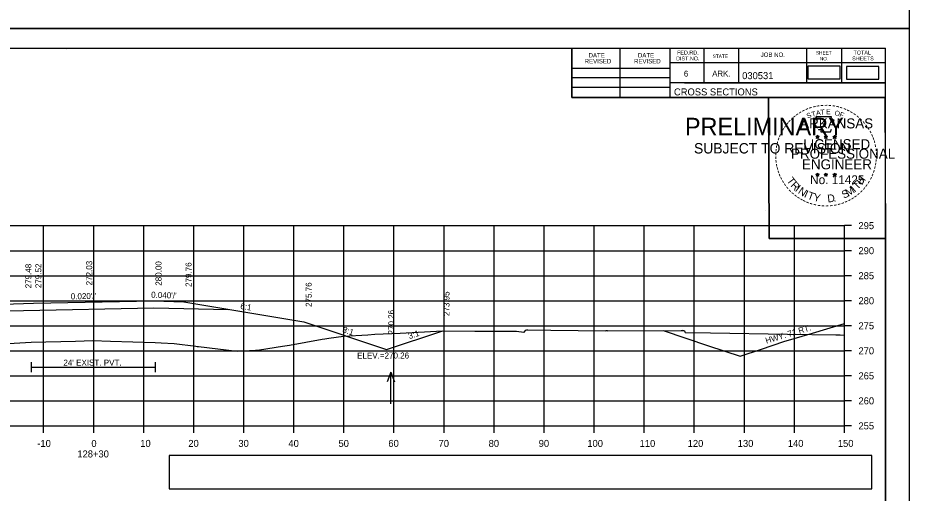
# Model space of a CAD drawing. Extents: x 285 to 4233, y -659 to 3710.
# Drawn here: x 524.1 to 702.2, y 1590.1 to 1685 of the extents above; entities that cross this region are included whole.
import ezdxf

# ---------------------------------------------------------------- set-up
doc = ezdxf.new("R2010")
doc.units = 0
for name, color, linetype in [('R_Alt Surface', 7, 'Continuous'), ('R_Axis', 7, 'Continuous'), ('R_Axis Annot', 7, 'Continuous'), ('R_Border', 7, 'Continuous'), ('R_Border PE', 7, 'Continuous'), ('R_Border Prem', 7, 'Continuous'), ('R_Exist Surface', 7, 'Continuous'), ('R_Fin Surface', 7, 'Continuous'), ('R_Grid', 7, 'Continuous'), ('R_No Plot', 7, 'Continuous'), ('R_Proposed Const Limits', 7, 'Continuous'), ('R_Water', 7, 'Continuous'), ('R_Water Annot', 7, 'Continuous'), ('R_Xsect Elev', 7, 'Continuous'), ('R_Xsect Slope', 7, 'Continuous')]:
    doc.layers.add(name, color=color, linetype=linetype)

msp = doc.modelspace()

# ---------------------------------------------------------------- linework, layer by layer
at = {"layer": 'R_Alt Surface'}
for points in [[(508.71, 1626.25), (517.28, 1626.42), (525.28, 1626.58), (551.28, 1627.1), (551.28, 1627.1), (557.28, 1626.98), (566.12, 1626.8)], [(526.81, 1616.22), (526.81, 1614.22)], [(551.58, 1616.22), (551.58, 1614.22)], [(526.81, 1615.22), (551.58, 1615.22)]]:
    msp.add_lwpolyline(points, dxfattribs=at)
at = {"layer": 'R_Axis'}
for p, q in [((689.28, 1603.52), (689.28, 1643.52)), ((690.68, 1643.52), (689.28, 1643.52)), ((690.68, 1638.52), (689.28, 1638.52)), ((690.68, 1633.52), (689.28, 1633.52)), ((690.68, 1628.52), (689.28, 1628.52)), ((690.68, 1623.52), (689.28, 1623.52)), ((690.68, 1618.52), (689.28, 1618.52)), ((690.68, 1613.52), (689.28, 1613.52)), ((690.68, 1608.52), (689.28, 1608.52)), ((389.28, 1603.52), (689.28, 1603.52)), ((529.28, 1602.12), (529.28, 1603.52)), ((539.28, 1602.12), (539.28, 1603.52)), ((549.28, 1602.12), (549.28, 1603.52)), ((559.28, 1602.12), (559.28, 1603.52)), ((569.28, 1602.12), (569.28, 1603.52)), ((579.28, 1602.12), (579.28, 1603.52)), ((589.28, 1602.12), (589.28, 1603.52)), ((599.28, 1602.12), (599.28, 1603.52)), ((609.28, 1602.12), (609.28, 1603.52)), ((619.28, 1602.12), (619.28, 1603.52)), ((629.28, 1602.12), (629.28, 1603.52)), ((639.28, 1602.12), (639.28, 1603.52)), ((649.28, 1602.12), (649.28, 1603.52)), ((659.28, 1602.12), (659.28, 1603.52)), ((669.28, 1602.12), (669.28, 1603.52)), ((679.28, 1602.12), (679.28, 1603.52)), ((689.28, 1602.12), (689.28, 1603.52)), ((690.68, 1603.52), (689.28, 1603.52))]:
    msp.add_line(p, q, dxfattribs=at)
at = {"layer": 'R_Axis Annot'}
for points in [[(681.96, 1672.82), (688.42, 1672.82), (688.42, 1675.38), (681.96, 1675.38)], [(689.66, 1672.76), (696.12, 1672.76), (696.12, 1675.32), (689.66, 1675.32)], [(554.36, 1590.93), (694.72, 1590.93), (694.72, 1597.58), (554.36, 1597.58)]]:
    msp.add_lwpolyline(points, close=True, dxfattribs=at)
at = {"layer": 'R_Border'}
for p, q in [((381.28, 1678.98), (697.46, 1678.98)), ((533.8, 1678.72), (533.8, 1678.72)), ((533.8, 1678.72), (533.8, 1678.72)), ((634.82, 1669.1), (634.82, 1678.98)), ((644.5, 1669.1), (644.5, 1678.98)), ((654.36, 1678.98), (654.36, 1669.1)), ((661.2, 1678.98), (661.2, 1672.04)), ((668.14, 1678.98), (668.14, 1672.04)), ((681.72, 1678.98), (681.72, 1672.04)), ((688.66, 1678.98), (688.66, 1672.04)), ((697.46, 1473.52), (697.46, 1678.98)), ((697.46, 1676.04), (654.36, 1676.04)), ((697.46, 1676.06), (697.46, 1676.06)), ((634.82, 1674.96), (654.36, 1674.96)), ((634.82, 1673.1), (654.36, 1673.1)), ((634.82, 1671.16), (654.36, 1671.16)), ((697.46, 1672.04), (654.36, 1672.04)), ((657.32, 1672.04), (697.46, 1672.04)), ((697.46, 1669.1), (634.82, 1669.1))]:
    msp.add_line(p, q, dxfattribs=at)
at = {"layer": 'R_Border PE'}
for p, q in [((683.89, 1661.61), (683.85, 1661.36)), ((683.89, 1661.24), (683.89, 1661.61)), ((683.89, 1661.61), (683.94, 1661.36)), ((685.56, 1661.61), (685.52, 1661.36)), ((685.56, 1661.24), (685.56, 1661.61)), ((685.56, 1661.61), (685.61, 1661.36)), ((687.33, 1661.6), (687.29, 1661.34)), ((687.33, 1661.23), (687.33, 1661.6)), ((687.33, 1661.6), (687.38, 1661.35)), ((683.54, 1661.35), (683.89, 1661.24)), ((683.54, 1661.35), (683.8, 1661.31)), ((683.54, 1661.35), (683.78, 1661.23)), ((683.68, 1660.95), (683.89, 1661.24)), ((683.68, 1660.95), (683.8, 1661.19)), ((683.68, 1660.95), (683.89, 1661.16)), ((684.24, 1661.35), (683.89, 1661.24)), ((684.11, 1660.95), (683.89, 1661.24)), ((684.11, 1660.95), (683.89, 1661.16)), ((684.24, 1661.35), (683.95, 1661.3)), ((684.11, 1660.95), (683.97, 1661.24)), ((684.24, 1661.35), (684.04, 1661.25)), ((685.21, 1661.35), (685.56, 1661.24)), ((685.21, 1661.35), (685.47, 1661.31)), ((685.21, 1661.35), (685.45, 1661.23)), ((685.35, 1660.95), (685.56, 1661.24)), ((685.35, 1660.95), (685.47, 1661.19)), ((685.35, 1660.95), (685.56, 1661.16)), ((685.91, 1661.35), (685.56, 1661.24)), ((685.78, 1660.95), (685.56, 1661.24)), ((685.78, 1660.95), (685.56, 1661.16)), ((685.91, 1661.35), (685.62, 1661.3)), ((685.78, 1660.95), (685.64, 1661.24)), ((685.91, 1661.35), (685.71, 1661.25)), ((686.98, 1661.34), (687.33, 1661.23)), ((686.98, 1661.34), (687.23, 1661.3)), ((686.98, 1661.34), (687.22, 1661.22)), ((687.11, 1660.93), (687.33, 1661.23)), ((687.11, 1660.93), (687.24, 1661.18)), ((687.11, 1660.93), (687.33, 1661.15)), ((687.67, 1661.34), (687.33, 1661.23)), ((687.54, 1660.93), (687.33, 1661.23)), ((687.54, 1660.93), (687.33, 1661.15)), ((687.67, 1661.34), (687.39, 1661.29)), ((687.54, 1660.93), (687.4, 1661.22)), ((687.67, 1661.34), (687.47, 1661.24)), ((683.54, 1653.78), (683.89, 1653.67)), ((683.54, 1653.78), (683.79, 1653.74)), ((683.54, 1653.78), (683.78, 1653.66)), ((683.67, 1653.37), (683.89, 1653.67)), ((683.67, 1653.37), (683.8, 1653.62)), ((683.67, 1653.37), (683.89, 1653.59)), ((683.89, 1654.03), (683.85, 1653.78)), ((683.89, 1653.67), (683.89, 1654.03)), ((683.89, 1654.03), (683.94, 1653.78)), ((684.24, 1653.78), (683.89, 1653.67)), ((684.1, 1653.37), (683.89, 1653.67)), ((684.1, 1653.37), (683.89, 1653.59)), ((684.24, 1653.78), (683.95, 1653.73)), ((684.1, 1653.37), (683.97, 1653.66)), ((684.24, 1653.78), (684.03, 1653.68)), ((685.21, 1653.78), (685.56, 1653.67)), ((685.21, 1653.78), (685.46, 1653.74)), ((685.21, 1653.78), (685.45, 1653.66)), ((685.34, 1653.37), (685.56, 1653.67)), ((685.34, 1653.37), (685.47, 1653.62)), ((685.34, 1653.37), (685.56, 1653.59)), ((685.56, 1654.03), (685.52, 1653.78)), ((685.56, 1653.67), (685.56, 1654.03)), ((685.56, 1654.03), (685.61, 1653.78)), ((685.91, 1653.78), (685.56, 1653.67)), ((685.77, 1653.37), (685.56, 1653.67)), ((685.77, 1653.37), (685.56, 1653.59)), ((685.91, 1653.78), (685.62, 1653.73)), ((685.77, 1653.37), (685.63, 1653.66)), ((685.91, 1653.78), (685.7, 1653.68)), ((686.98, 1653.77), (687.33, 1653.66)), ((686.98, 1653.77), (687.23, 1653.73)), ((686.98, 1653.77), (687.21, 1653.65)), ((687.11, 1653.36), (687.33, 1653.66)), ((687.11, 1653.36), (687.24, 1653.61)), ((687.11, 1653.36), (687.32, 1653.58)), ((687.33, 1654.02), (687.28, 1653.77)), ((687.54, 1653.36), (687.32, 1653.58)), ((687.33, 1653.66), (687.33, 1654.02)), ((687.33, 1654.02), (687.37, 1653.77)), ((687.67, 1653.77), (687.33, 1653.66)), ((687.54, 1653.36), (687.33, 1653.66)), ((687.67, 1653.77), (687.39, 1653.72)), ((687.54, 1653.36), (687.4, 1653.65)), ((687.67, 1653.77), (687.47, 1653.67))]:
    msp.add_line(p, q, dxfattribs=at)
for points in [[(683.59, 1665.23), (683.85, 1664.4)], [(687.1, 1664.31), (687.24, 1664.59), (686.55, 1664.57), (686.7, 1665.23), (683.59, 1665.23)], [(683.89, 1661.61), (684.11, 1660.95), (683.54, 1661.35), (684.24, 1661.35), (683.68, 1660.95), (683.89, 1661.61)], [(684.08, 1662.81), (684.08, 1662.72), (684.64, 1662.7), (684.59, 1662.23), (686.46, 1662.23), (686.66, 1662.77)], [(685.56, 1661.61), (685.78, 1660.95), (685.21, 1661.35), (685.91, 1661.35), (685.35, 1660.95), (685.56, 1661.61)], [(687.33, 1661.6), (687.54, 1660.93), (686.98, 1661.34), (687.67, 1661.34), (687.11, 1660.93), (687.33, 1661.6)], [(683.89, 1654.03), (684.1, 1653.37), (683.54, 1653.78), (684.24, 1653.78), (683.67, 1653.37), (683.89, 1654.03)], [(685.56, 1654.03), (685.77, 1653.37), (685.21, 1653.78), (685.91, 1653.78), (685.34, 1653.37), (685.56, 1654.03)], [(687.33, 1654.02), (687.54, 1653.36), (686.98, 1653.77), (687.67, 1653.77), (687.11, 1653.36), (687.33, 1654.02)]]:
    msp.add_lwpolyline(points, dxfattribs=at)
for centre, radius in [((683.89, 1661.24), 0.172), ((683.89, 1661.24), 0.145), ((683.89, 1661.24), 0.116), ((683.89, 1661.24), 0.0991), ((683.89, 1661.24), 0.0747), ((683.89, 1661.24), 0.0495), ((683.89, 1661.24), 0.0296), ((685.56, 1661.24), 0.172), ((685.56, 1661.24), 0.145), ((685.56, 1661.24), 0.116), ((685.56, 1661.24), 0.0991), ((685.56, 1661.24), 0.0747), ((685.56, 1661.24), 0.0495), ((685.56, 1661.24), 0.0296), ((687.33, 1661.23), 0.172), ((687.33, 1661.23), 0.145), ((687.33, 1661.23), 0.116), ((687.33, 1661.23), 0.0991), ((687.33, 1661.23), 0.0747), ((687.33, 1661.23), 0.0495), ((687.33, 1661.23), 0.0296), ((683.89, 1653.67), 0.172), ((683.89, 1653.67), 0.145), ((683.89, 1653.67), 0.116), ((683.89, 1653.67), 0.0991), ((683.89, 1653.67), 0.0747), ((683.89, 1653.67), 0.0495), ((683.89, 1653.67), 0.0296), ((685.56, 1653.67), 0.172), ((685.56, 1653.67), 0.145), ((685.56, 1653.67), 0.116), ((685.56, 1653.67), 0.0991), ((685.56, 1653.67), 0.0747), ((685.56, 1653.67), 0.0495), ((685.56, 1653.67), 0.0296), ((687.32, 1653.66), 0.172), ((687.32, 1653.66), 0.145), ((687.32, 1653.66), 0.116), ((687.32, 1653.66), 0.0991), ((687.32, 1653.66), 0.0747), ((687.32, 1653.66), 0.0495), ((687.32, 1653.66), 0.0296)]:
    msp.add_circle(centre, radius, dxfattribs=at)
at = {"layer": 'R_Exist Surface'}
msp.add_lwpolyline([(517.68, 1619.7), (526.81, 1620.22), (535.67, 1620.46), (539.11, 1620.55), (542.66, 1620.45), (551.58, 1620.21), (552.74, 1620.13), (555.39, 1619.95), (559.66, 1619.42), (559.93, 1619.39), (560.23, 1619.35), (567.97, 1618.47), (571.64, 1618.68), (572.38, 1618.71), (577.02, 1619.43), (578.38, 1619.65), (584.93, 1620.83), (585.47, 1620.93), (586.26, 1621.04), (589.18, 1621.45), (594.03, 1621.73), (595.45, 1621.81), (600.53, 1622.05), (608.99, 1622.48), (615.4, 1622.47), (623.77, 1622.45), (625.25, 1622.26), (625.3, 1622.25), (625.3, 1622.26), (625.61, 1622.65), (625.84, 1622.7), (625.84, 1622.7), (625.84, 1622.7), (626.05, 1622.68), (630.64, 1622.64), (641.53, 1622.54), (641.7, 1622.56), (641.87, 1622.55), (642.02, 1622.54), (656.78, 1622.55), (656.78, 1622.58), (656.78, 1622.6), (656.78, 1622.61), (656.85, 1622.6), (656.92, 1622.57), (657.15, 1622.56), (657.33, 1622.54), (657.36, 1622.33), (657.43, 1622.15), (662.55, 1622.12), (677.89, 1621.86), (687.53, 1621.72), (688.45, 1621.69), (689.28, 1621.66)], dxfattribs=at)
at = {"layer": 'R_Fin Surface'}
for points in [[(467.65, 1615.25), (468.82, 1614.86), (497.28, 1624.35), (517.28, 1627.68), (525.28, 1628), (527.28, 1628.04), (551.28, 1628.52), (557.28, 1628.28), (581.28, 1624.28), (597.77, 1618.78), (608.82, 1622.47)], [(653.06, 1622.55), (662.1, 1619.54), (668.42, 1617.43), (672.68, 1618.85), (677.17, 1620.35), (682.89, 1622.07), (689.28, 1623.96)]]:
    msp.add_lwpolyline(points, dxfattribs=at)
at = {"layer": 'R_Grid'}
for p, q in [((389.28, 1643.52), (689.28, 1643.52)), ((529.28, 1603.52), (529.28, 1643.52)), ((539.28, 1603.52), (539.28, 1643.52)), ((549.28, 1603.52), (549.28, 1643.52)), ((559.28, 1603.52), (559.28, 1643.52)), ((569.28, 1603.52), (569.28, 1643.52)), ((579.28, 1603.52), (579.28, 1643.52)), ((589.28, 1603.52), (589.28, 1643.52)), ((599.28, 1603.52), (599.28, 1643.52)), ((609.28, 1603.52), (609.28, 1643.52)), ((619.28, 1603.52), (619.28, 1643.52)), ((629.28, 1603.52), (629.28, 1643.52)), ((639.28, 1603.52), (639.28, 1643.52)), ((649.28, 1603.52), (649.28, 1643.52)), ((659.28, 1603.52), (659.28, 1643.52)), ((669.28, 1603.52), (669.28, 1643.52)), ((679.28, 1603.52), (679.28, 1643.52)), ((689.28, 1603.52), (689.28, 1643.52)), ((389.28, 1638.52), (689.28, 1638.52)), ((389.28, 1633.52), (689.28, 1633.52)), ((389.28, 1628.52), (689.28, 1628.52)), ((389.28, 1623.52), (689.28, 1623.52)), ((389.28, 1618.52), (689.28, 1618.52)), ((389.28, 1613.52), (689.28, 1613.52)), ((389.28, 1608.52), (689.28, 1608.52)), ((389.28, 1603.52), (689.28, 1603.52))]:
    msp.add_line(p, q, dxfattribs=at)
at = {"layer": 'R_No Plot'}
for p, q in [((368.88, 1682.88), (702.21, 1682.88)), ((368.88, 1682.87), (702.21, 1682.87)), ((673.49, 1646.64), (673.49, 1646.64))]:
    msp.add_line(p, q, dxfattribs=at)
for points in [[(368.87, 1896.21), (702.21, 1896.21), (702.21, 1682.87), (368.87, 1682.87)], [(368.87, 1682.87), (702.21, 1682.87), (702.21, 1469.54), (368.87, 1469.54)], [(615.2, 1678.98), (634.82, 1678.98), (634.82, 1669.1), (650.93, 1669.1), (674.13, 1669.1), (674.25, 1640.94), (697.46, 1640.94), (697.46, 1473.52), (381.28, 1473.52), (381.28, 1678.98)], [(674.13, 1669.1), (697.34, 1669.1), (697.46, 1640.94), (674.25, 1640.94)]]:
    msp.add_lwpolyline(points, close=True, dxfattribs=at)
at = {"layer": 'R_Proposed Const Limits'}
for points in [[(527.28, 1628.04), (527.28, 1628.04), (527.28, 1628.04)], [(551.28, 1628.52), (551.28, 1628.52), (551.28, 1628.52)]]:
    msp.add_lwpolyline(points, dxfattribs=at)
at = {"layer": 'R_Water Annot'}
for p, q in [((598.65, 1614.24), (597.95, 1612.31)), ((598.65, 1607.95), (598.65, 1614.24)), ((598.65, 1614.24), (599.35, 1612.31))]:
    msp.add_line(p, q, dxfattribs=at)
at = {"layer": 'R_Xsect Elev'}
msp.add_line((539.28, 1620.54), (539.28, 1637.93), dxfattribs=at)

# ---------------------------------------------------------------- texts
at = {"layer": 'R_Axis Annot'}
for s, p in [('295', (692.08, 1642.82)), ('290', (692.08, 1637.82)), ('285', (692.08, 1632.82)), ('280', (692.08, 1627.82)), ('275', (692.08, 1622.82)), ('270', (692.08, 1617.82)), ('265', (692.08, 1612.82)), ('260', (692.08, 1607.82)), ('255', (692.08, 1602.82)), ('-10', (528.02, 1599.32)), ('0', (538.82, 1599.32)), ('10', (548.59, 1599.32)), ('20', (558.19, 1599.32)), ('30', (568.19, 1599.32)), ('40', (578.19, 1599.32)), ('50', (588.19, 1599.32)), ('60', (598.16, 1599.32)), ('70', (608.19, 1599.32)), ('80', (618.19, 1599.32)), ('90', (628.19, 1599.32)), ('100', (637.91, 1599.32)), ('110', (648.36, 1599.32)), ('120', (657.96, 1599.32)), ('130', (667.96, 1599.32)), ('140', (677.96, 1599.32)), ('150', (687.96, 1599.32)), ('128+30', (536.02, 1597.22))]:
    msp.add_text(s, height=1.4, dxfattribs=at).set_placement(p)
at = {"layer": 'R_Border'}
for s, height, p in [('DATE', 0.879, (638.16, 1677.11)), ('DATE', 0.879, (648.02, 1677.11)), ('FED.RD.', 0.782, (655.84, 1677.7)), ('STATE', 0.684, (662.96, 1677.02)), ('JOB NO.', 0.879, (672.54, 1677.22)), ('SHEET', 0.684, (683.58, 1677.7)), ('TOTAL', 0.782, (691.1, 1677.7)), ('REVISED', 0.879, (637.38, 1675.93)), ('REVISED', 0.879, (647.24, 1675.93)), ('DIST.NO.', 0.782, (655.64, 1676.52)), ('NO.', 0.684, (684.36, 1676.52)), ('SHEETS', 0.782, (690.82, 1676.52)), ('6', 1.17, (657.2, 1673.3)), ('ARK.', 1.172, (662.86, 1673.3)), ('030531', 1.4, (668.84, 1672.78)), ('CROSS SECTIONS', 1.4, (655.22, 1669.53))]:
    msp.add_text(s, height=height, rotation=360, dxfattribs=at).set_placement(p)
at = {"layer": 'R_Border PE'}
for s, height, rotation, p in [('-', 1.6, 24.3072, (681.7, 1666.09)), ('-', 1.6, 19.1761, (682.33, 1666.36)), ('-', 1.6, 13.6301, (683.08, 1666.6)), ('-', 1.6, 10.2193, (683.76, 1666.76)), ('-', 1.6, 5.8968, (684.49, 1666.87)), ('-', 1.6, 0.1862, (685.26, 1666.94)), ('-', 1.6, 357.743, (685.98, 1666.93)), ('-', 1.6, 352.1617, (686.73, 1666.87)), ('-', 1.6, 347.2049, (687.45, 1666.76)), ('-', 1.6, 342.3362, (688.08, 1666.61)), ('-', 1.6, 337.8551, (688.82, 1666.38)), ('-', 1.6, 42.9622, (678.98, 1664.21)), ('-', 1.6, 38.9507, (679.41, 1664.63)), ('-', 1.6, 36.2317, (679.89, 1665.01)), ('-', 1.6, 34.0636, (680.47, 1665.4)), ('-', 1.6, 28.7918, (681.07, 1665.77)), ('S', 1, 21.594, (681.94, 1664.91)), ('T', 1, 16.4036, (682.85, 1665.24)), ('A', 1, 11.2132, (683.68, 1665.49)), ('T', 1, 6.0228, (684.53, 1665.66)), ('E', 1, 0.8323, (685.63, 1665.77)), ('O', 1, 350.4515, (687.24, 1665.56)), ('F', 1, 340.0707, (688.19, 1665.33)), ('-', 1.6, 334.1211, (689.45, 1666.11)), ('-', 1.6, 329.6409, (690.03, 1665.83)), ('-', 1.6, 325.8627, (690.67, 1665.47)), ('-', 1.6, 320.5297, (691.28, 1665.04)), ('-', 1.6, 54.2325, (677.72, 1662.68)), ('-', 1.6, 50.6142, (678.13, 1663.25)), ('-', 1.6, 48.423, (678.53, 1663.73)), ('ARKANSAS', 2, 360, (680.44, 1662.94)), ('-', 1.6, 315.5786, (691.88, 1664.55)), ('-', 1.6, 309.8797, (692.45, 1664)), ('-', 1.6, 306.6522, (692.97, 1663.4)), ('-', 1.6, 67.7743, (676.82, 1660.93)), ('-', 1.6, 62.8713, (677.08, 1661.54)), ('-', 1.6, 58.0706, (677.39, 1662.15)), ('-', 1.4, 303.6753, (693.46, 1662.83)), ('-', 1.6, 299.6684, (693.78, 1662.23)), ('-', 1.6, 294.6628, (694.1, 1661.61)), ('-', 1.6, 75.461, (676.4, 1659.59)), ('-', 1.6, 72.3945, (676.6, 1660.3)), ('LICENSED', 2, 360, (681.04, 1658.79)), ('DWB', 0.01, 360, (683.88, 1661.24)), ('DWB', 0.01, 360, (685.55, 1661.24)), ('DWB', 0.01, 360, (687.31, 1661.23)), ('-', 1.6, 290.5728, (694.36, 1661.04)), ('-', 1.6, 285.1233, (694.59, 1660.46)), ('-', 1.6, 89.0622, (676.17, 1657.48)), ('-', 1.6, 85.1863, (676.2, 1658.18)), ('-', 1.6, 81.2013, (676.27, 1658.87)), ('PROFESSIONAL', 2, 360, (678.61, 1656.89)), ('-', 1.6, 280.5493, (694.79, 1659.72)), ('-', 1.6, 276.5962, (694.96, 1658.95)), ('-', 1.6, 274.3301, (695.02, 1658.23)), ('-', 1.6, 94.1959, (676.21, 1656.76)), ('-', 1.6, 98.9479, (676.28, 1656.09)), ('ENGINEER', 2, 360, (680.8, 1654.77)), ('-', 1.6, 263.5172, (695.03, 1656.93)), ('-', 1.6, 269.9407, (695.05, 1657.59)), ('-', 1.6, 101.7149, (676.41, 1655.36)), ('-', 1.6, 105.4578, (676.58, 1654.76)), ('-', 1.6, 109.0874, (676.79, 1654.13)), ('-', 1.6, 252.8681, (694.67, 1654.88)), ('-', 1.6, 255.7626, (694.85, 1655.6)), ('-', 1.6, 260.9953, (694.96, 1656.27)), ('-', 1.6, 114.0643, (677.04, 1653.53)), ('-', 1.6, 115.7289, (677.35, 1652.92)), ('T', 1.54, 306.0406, (677.65, 1652.51)), ('No. 11425', 1.757, 360, (682.43, 1651.81)), ('DWB', 0.01, 360, (683.88, 1653.66)), ('DWB', 0.01, 360, (685.55, 1653.66)), ('DWB', 0.01, 360, (687.31, 1653.65)), ('H', 1.54, 54.6088, (692.77, 1651.54)), ('-', 1.6, 244.6197, (694.18, 1653.57)), ('-', 1.6, 247.8887, (694.45, 1654.2)), ('-', 1.6, 120.4471, (677.71, 1652.33)), ('-', 1.6, 125.8934, (678.11, 1651.77)), ('-', 1.6, 130.7181, (678.57, 1651.22)), ('R', 1.54, 314.005, (678.41, 1651.46)), ('I', 1.54, 321.9694, (679.31, 1650.53)), ('N', 1.54, 326.5002, (679.88, 1650.06)), ('M', 1.54, 32.6563, (690.03, 1649.28)), ('I', 1.54, 42.1136, (691.32, 1650.12)), ('T', 1.54, 46.6444, (691.88, 1650.6)), ('-', 1.6, 231.2538, (692.96, 1651.6)), ('-', 1.6, 233.8452, (693.39, 1652.17)), ('-', 1.6, 239.0712, (693.79, 1652.82)), ('-', 1.6, 134.2238, (679.09, 1650.67)), ('-', 1.6, 138.9338, (679.61, 1650.21)), ('-', 1.6, 144.6463, (680.17, 1649.8)), ('-', 1.6, 148.0898, (680.73, 1649.43)), ('I', 1.54, 335.3603, (681.09, 1649.27)), ('T', 1.54, 339.8912, (681.75, 1648.94)), ('Y', 1.54, 347.8556, (682.97, 1648.5)), ('D', 1.54, 6.3969, (685.95, 1648.14)), ('S', 1.54, 26.9312, (689.19, 1648.87)), ('-', 1.6, 212.2491, (690.87, 1649.67)), ('-', 1.6, 215.7363, (691.41, 1650.06)), ('-', 1.6, 221.0851, (691.96, 1650.53)), ('-', 1.6, 225.7653, (692.48, 1651.04)), ('-', 1.6, 151.5704, (681.31, 1649.11)), ('-', 1.6, 154.6002, (681.83, 1648.86)), ('-', 1.6, 158.5612, (682.46, 1648.6)), ('-', 1.6, 162.7983, (683.14, 1648.39)), ('-', 1.6, 167.5555, (683.86, 1648.23)), ('-', 1.6, 173.1155, (684.63, 1648.12)), ('-', 1.6, 176.5183, (685.38, 1648.06)), ('-', 1.6, 181.5918, (686.12, 1648.08)), ('-', 1.6, 185.8167, (686.93, 1648.16)), ('-', 1.6, 191.2858, (687.67, 1648.29)), ('.', 1.54, 13.7642, (687.14, 1648.27)), ('-', 1.6, 195.4743, (688.4, 1648.49)), ('-', 1.6, 200.7184, (689.07, 1648.73)), ('-', 1.6, 204.2516, (689.69, 1649.01)), ('-', 1.6, 207.3568, (690.32, 1649.32))]:
    msp.add_text(s, height=height, rotation=rotation, dxfattribs=at).set_placement(p)
at = {"layer": 'R_Border Prem'}
for s, height, p in [('PRELIMINARY', 3.5, (657.41, 1661.56)), ('DWB', 0.01, (658.16, 1663.41)), ('SUBJECT TO REVISION', 2.0751, (659.22, 1657.93))]:
    msp.add_text(s, height=height, rotation=360, dxfattribs=at).set_placement(p)
at = {"layer": 'R_Water'}
msp.add_text('HWY. 71 RT.', height=1.2, rotation=16.706, dxfattribs=at).set_placement((673.69, 1619.93))
msp.add_text("24' EXIST. PVT.", height=1.2, dxfattribs=at).set_placement((533.23, 1615.56))
at = {"layer": 'R_Xsect Elev'}
for s, p in [('279.48', (526.83, 1631)), ('279.52', (528.83, 1631.04)), ('272.03', (538.98, 1631.59)), ('280.00', (552.83, 1631.52)), ('279.76', (558.83, 1631.28)), ('275.76', (582.83, 1627.28)), ('273.95', (610.37, 1625.47)), ('270.26', (599.32, 1621.78))]:
    msp.add_text(s, height=1.2, rotation=90, dxfattribs=at).set_placement(p)
msp.add_text('ELEV.=270.26', height=1.2, dxfattribs=at).set_placement((591.91, 1616.98))
at = {"layer": 'R_Xsect Slope'}
for s, rotation, p in [("0.020'/'", 1.1458, (534.71, 1628.79)), ("0.040'/'", 357.7094, (550.74, 1629.14)), ('6:1', 350.5377, (568.51, 1626.91)), ('3:1', 341.5651, (588.89, 1622.27)), ('3:1', 18.4349, (602.35, 1620.84))]:
    msp.add_text(s, height=1.2, rotation=rotation, dxfattribs=at).set_placement(p)

doc.saveas('drawing.dxf')
